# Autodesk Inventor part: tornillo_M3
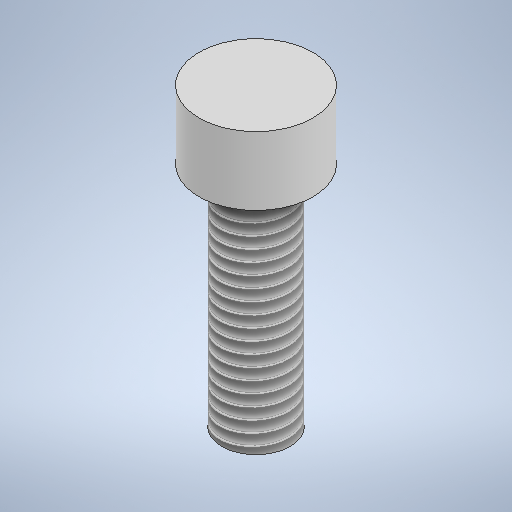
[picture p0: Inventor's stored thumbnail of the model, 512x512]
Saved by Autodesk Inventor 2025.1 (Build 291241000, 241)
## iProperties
Created: 2025-04
Part Number: tornillo_M3
Material: Genérico
Document SubType Name: Modeling
Designer: Usuario
Density: 1 g/cm^3
Appearance: Valor por defecto
Author: Usuario
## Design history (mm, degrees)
sketch "Boceto1"
  geometry: C1 r 1.5 at (0, 0); 1 further point
  constraints: 1 centre point, 1 coincident
  dimensions: "d0" = 3 diameter of C1
extrude "Extrusión1" new body sketch "Boceto1" distance "d1" = 10; taper "d2" = 0 deg
node "Plano de trabajo1"
sketch "Boceto2"
  geometry: C1 r 1.5 at (0, 0) reference; C2 r 2.5 at (0, 0); 1 further point
  constraints: 1 centre point, 1 coincident
  dimensions: "d4" = 5 diameter of C2
extrude "Extrusión2" join sketch "Boceto2" distance "d5" = 3; taper "d6" = 0 deg
feature "Rosca1" dims "d7" = 10, "d8" = 0
node "Sólido1"
other parameters: "d3" = 0
